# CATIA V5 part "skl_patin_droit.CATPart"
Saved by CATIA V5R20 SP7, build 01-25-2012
Part number: skl_patin_droit
Publications: "Axe_pivot_patin_droit_bras_droit", "Plan.1"
Bounding box of the stored display mesh (mm): x 350 to 524.226, y 0 to 0, z 0 to 20
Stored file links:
  U:\IAO\thinkmotion catia2\skl_patin_droit.CATPart
  U:\IAO\thinkmotion catia2\skl_862_adubourgno.CATProduct
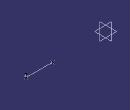
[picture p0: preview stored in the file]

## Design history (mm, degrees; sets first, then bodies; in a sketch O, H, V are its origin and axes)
Set1
  Point1 "J": linked copy from another document
  Point2 "M": linked copy from another document
  Plane1: linked copy from another document
Set2
  Line1: type PtPt, FirstPoint Point1, SecondPoint Point2
  Line2 "Axe_pivot_patin_droit_bras_droit": type Normal, RefPoint Point1, RefSkin Plane1, Start 0, End 20
Body1 (main body)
